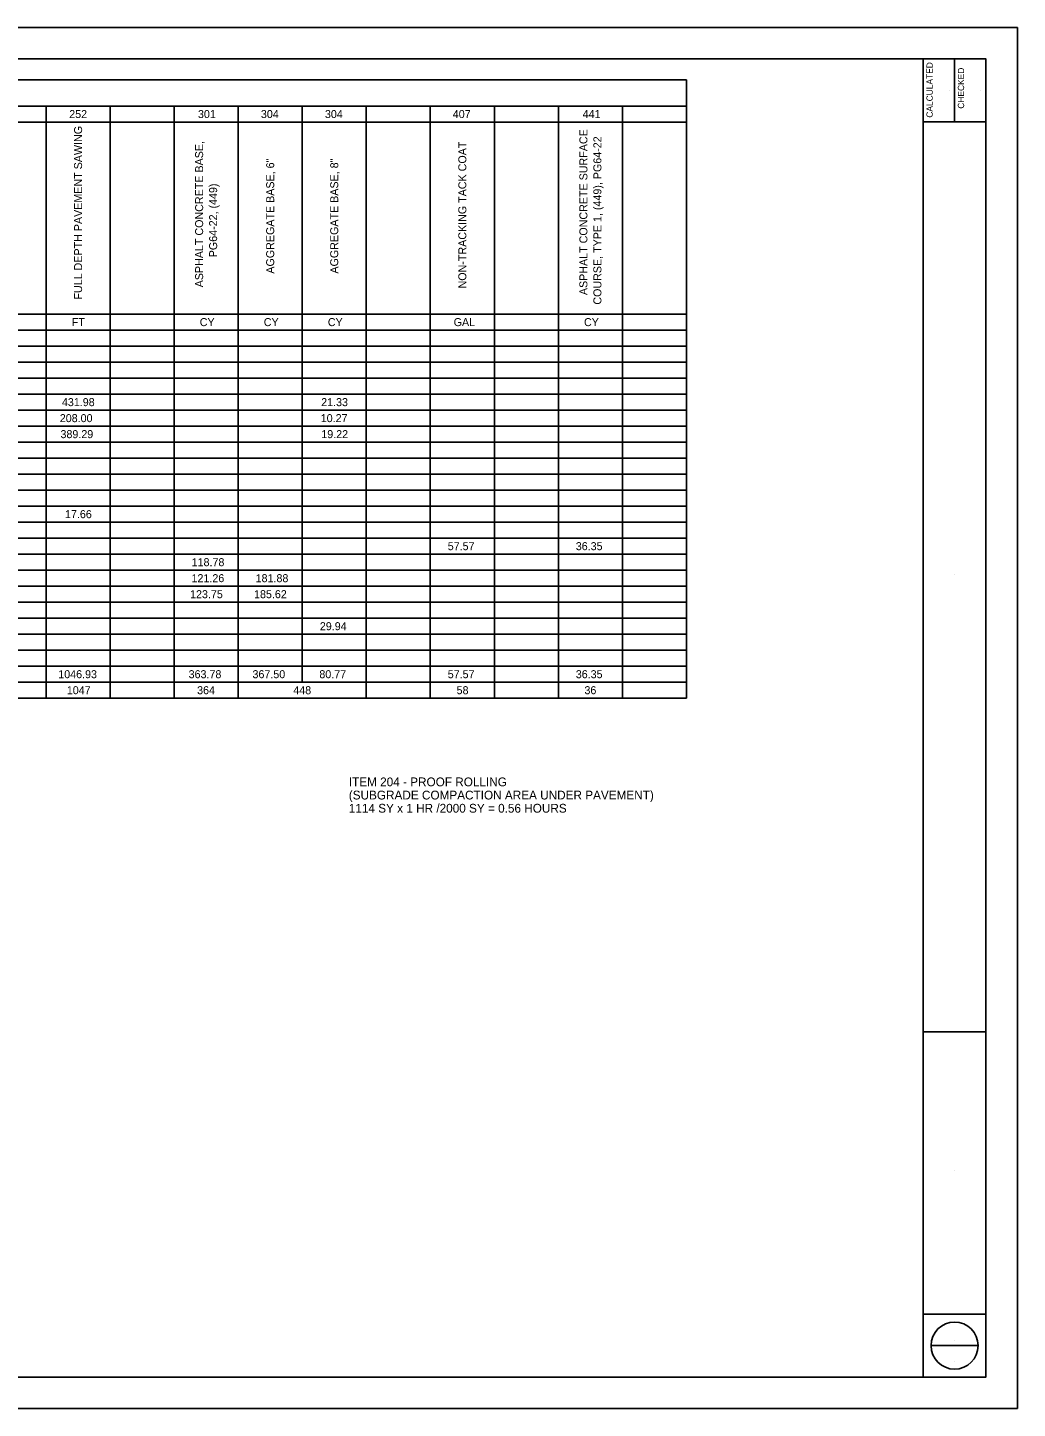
# Model space of a CAD drawing. Extents: x 0 to 34, y 0 to 22.
# Drawn here: x 18.24 to 34, y 0 to 22 of the extents above; entities that cross this region are included whole.
import ezdxf

# ---------------------------------------------------------------- set-up
doc = ezdxf.new("R2010")
doc.units = 0
for name, color, linetype in [('SH_Border', 7, 'Continuous'), ('SH_Cut_Line', 7, 'Continuous'), ('SH_Data', 7, 'Continuous'), ('SH_Text', 7, 'Continuous')]:
    doc.layers.add(name, color=color, linetype=linetype)

msp = doc.modelspace()

# ---------------------------------------------------------------- linework, layer by layer
at = {"layer": 'SH_Border'}
for p, q in [((32.5, 0.5), (32.5, 21.5)), ((33, 21.5), (33, 20.5)), ((32.5, 20.5), (33.5, 20.5)), ((32.5, 6), (33.5, 6)), ((32.5, 1.5), (33.5, 1.5))]:
    msp.add_line(p, q, dxfattribs=at)
msp.add_lwpolyline([(2, 21.5), (33.5, 21.5), (33.5, 0.5), (2, 0.5)], close=True, dxfattribs=at)
at = {"layer": 'SH_Cut_Line'}
msp.add_lwpolyline([(0, 0), (34, 0), (34, 22), (0, 22)], close=True, dxfattribs=at)
at = {"layer": 'SH_Data'}
for p, q in [((32.92, 21.004), (32.92, 21.004)), ((33.42, 21.004), (33.42, 21.004)), ((2, 20.75), (28.73, 20.75)), ((18.53, 20.75), (18.53, 11.315)), ((19.55, 20.75), (19.55, 11.315)), ((20.57, 20.75), (20.57, 11.315)), ((21.59, 20.75), (21.59, 11.315)), ((22.61, 20.75), (22.61, 11.57)), ((23.63, 20.75), (23.63, 11.315)), ((24.65, 20.75), (24.65, 11.315)), ((25.67, 20.75), (25.67, 11.315)), ((26.69, 20.75), (26.69, 11.315)), ((27.71, 20.75), (27.71, 11.315)), ((28.73, 20.75), (28.73, 11.315)), ((11.39, 20.495), (28.73, 20.495)), ((7.31, 17.435), (28.73, 17.435)), ((2, 17.18), (28.73, 17.18)), ((2, 16.925), (28.73, 16.925)), ((2, 16.67), (28.73, 16.67)), ((2, 16.415), (28.73, 16.415)), ((2, 16.16), (28.73, 16.16)), ((2, 15.905), (28.73, 15.905)), ((2, 15.65), (28.73, 15.65)), ((2, 15.395), (28.73, 15.395)), ((2, 15.14), (28.73, 15.14)), ((2, 14.885), (28.73, 14.885)), ((2, 14.63), (28.73, 14.63)), ((2, 14.375), (28.73, 14.375)), ((2, 14.12), (28.73, 14.12)), ((2, 13.865), (28.73, 13.865)), ((2, 13.61), (28.73, 13.61)), ((2, 13.355), (28.73, 13.355)), ((33, 13.292), (33, 13.292)), ((2, 13.1), (28.73, 13.1)), ((2, 12.845), (28.73, 12.845)), ((2, 12.59), (28.73, 12.59)), ((2, 12.335), (28.73, 12.335)), ((2, 12.08), (28.73, 12.08)), ((2, 11.825), (28.73, 11.825)), ((2, 11.57), (28.73, 11.57)), ((2, 11.315), (28.73, 11.315)), ((33, 3.792), (33, 3.792)), ((32.625, 1), (33.375, 1)), ((33, 1.085), (33, 1.085)), ((33, 0.745), (33, 0.745))]:
    msp.add_line(p, q, dxfattribs=at)
msp.add_circle((33, 1), 0.375, dxfattribs=at)
at = {"layer": 'SH_Text'}
msp.add_lwpolyline([(2, 20.75), (28.73, 20.75), (28.73, 21.168), (2, 21.168)], close=True, dxfattribs=at)

# ---------------------------------------------------------------- texts
at = {"layer": 'SH_Data'}
for s, p in [('CALCULATED', (32.652, 20.565)), ('CHECKED', (33.152, 20.708))]:
    msp.add_text(s, height=0.1, rotation=90, dxfattribs=at).set_placement(p)
at = {"layer": 'SH_Text'}
for s, height, p in [('252', 0.1275, (18.899, 20.559)), ('301', 0.1275, (20.95, 20.559)), ('304', 0.1275, (21.952, 20.559)), ('304', 0.1275, (22.972, 20.559)), ('407', 0.1275, (25.008, 20.559)), ('441', 0.1275, (27.076, 20.559)), ('FT', 0.1275, (18.94, 17.244)), ('CY', 0.1275, (20.978, 17.244)), ('CY', 0.1275, (21.998, 17.244)), ('CY', 0.1275, (23.018, 17.244)), ('GAL', 0.1275, (25.022, 17.244)), ('CY', 0.1275, (27.098, 17.244)), ('431.98', 0.1275, (18.783, 15.969)), ('21.33', 0.1275, (22.912, 15.969)), ('208.00', 0.1275, (18.749, 15.714)), ('10.27', 0.1275, (22.905, 15.714)), ('389.29', 0.1275, (18.76, 15.459)), ('19.22', 0.1275, (22.914, 15.459)), ('17.66', 0.1275, (18.832, 14.184)), ('57.57', 0.1275, (24.928, 13.674)), ('36.35', 0.1275, (26.967, 13.674)), ('118.78', 0.1275, (20.849, 13.419)), ('121.26', 0.1275, (20.847, 13.164)), ('181.88', 0.1275, (21.868, 13.164)), ('123.75', 0.1275, (20.824, 12.909)), ('185.62', 0.1275, (21.843, 12.909)), ('29.94', 0.1275, (22.891, 12.399)), ('1046.93', 0.1275, (18.725, 11.634)), ('363.78', 0.1275, (20.801, 11.634)), ('367.50', 0.1275, (21.818, 11.634)), ('80.77', 0.1275, (22.883, 11.634)), ('57.57', 0.1275, (24.928, 11.634)), ('36.35', 0.1275, (26.967, 11.634)), ('1047', 0.1275, (18.861, 11.379)), ('364', 0.1275, (20.936, 11.379)), ('448', 0.1275, (22.468, 11.379)), ('58', 0.1275, (25.069, 11.379)), ('36', 0.1275, (27.105, 11.379)), ('ITEM 204 - PROOF ROLLING', 0.14, (23.352, 9.912)), ('(SUBGRADE COMPACTION AREA UNDER PAVEMENT)', 0.14, (23.352, 9.702)), ('1114 SY x 1 HR /2000 SY = 0.56 HOURS', 0.14, (23.352, 9.492))]:
    msp.add_text(s, height=height, dxfattribs=at).set_placement(p)
for s, p in [('FULL DEPTH PAVEMENT SAWING', (19.104, 17.667)), ('ASPHALT CONCRETE SURFACE', (27.152, 17.738)), ('COURSE, TYPE 1, (449), PG64-22', (27.375, 17.586)), ('ASPHALT CONCRETE BASE,', (21.032, 17.862)), ('NON-TRACKING TACK COAT', (25.224, 17.844)), ('AGGREGATE BASE, 6"', (22.164, 18.08)), ('AGGREGATE BASE, 8"', (23.184, 18.081)), ('PG64-22, (449)', (21.255, 18.341))]:
    msp.add_text(s, height=0.1275, rotation=90, dxfattribs=at).set_placement(p)

doc.saveas('drawing.dxf')
